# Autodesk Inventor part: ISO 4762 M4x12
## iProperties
Created: 2001-01
Part Number: ISO 4762 M4x12
Material: Steel, Mild
Document SubType Name: Modeling
Description: Bolt M4x12 ISO 4762
Standard: ISO 4762
Density: 7.86 g/cm^3
+MSCProtocol1+ProtocolID: P05030915110493789
+MSCProtocol2+Protocol: P05030915110493789<@PID>[Data]<@EL>mass=0.0022685837{kg<@EL>b=10.60{mm<@EL>r2=0.40{mm<@EL>r1=0.20{mm<@EL>s=3.00{mm<@EL>t=2.00{mm<@EL>k=4.00{mm<@EL>Dh=7.00{mm<@E
Control State: 0
Master: False
Checked Out: False
Shininess: 20.0
Length Units: 11269
Angle Units: 11279
Time Units: 11290
Mass Units: 11283
Length Display Precision: 3
Angle Display Precision: 2
BOM1: Bolt
BOM2: M4x12
BOM3: ISO 4762
Density: 7.86
Volumn: 2.805817155661937
Area: 16.25312931541364
PropertySet Name: Model Information
Revision Number: 1
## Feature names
1. ExtrusionBlind1
2. Chamfer1
3. ExtrusionBlind2
4. ExtrusionBlind3
5. Fillet1
6. Fillet2
